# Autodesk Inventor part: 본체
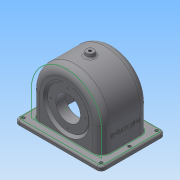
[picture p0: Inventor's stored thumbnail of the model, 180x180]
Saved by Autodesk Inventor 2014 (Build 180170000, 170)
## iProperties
Created: 2015-09
Part Number: 본체
Material: Generic
Document SubType Name: Modeling
Designer: sda1
Density: 1 g/cm^3
Appearance: Default
Author: sda1
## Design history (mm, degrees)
sketch "스케치7"
  geometry: L1 (0, 0)-(0, -40); L2 (-57, -40)-(57, -40); L3 (-57, -40)-(-57, 0); L4 (57, -40)-(57, 0); C1 r 51 at (0, 0); A1 r 57 centre (0, 0) between (-57, 0) and (57, 0)
  constraints: 8 end point, 2 centre point, 2 perpendicular, 2 point on circle, 1 coincident, 1 midpoint, 1 parallel, 1 vertical
  dimensions: "d18" = 40 distance of L1.end L1.start; "d19" = 114 distance of L2.start L2.end; "d20" = 102 diameter of C1; "d21" = 6 radial gap between concentric circles of C1 A1
extrude "돌출3" new body sketch "스케치7" distance "d22" = 77; taper "d23" = 0 deg
feature "쉘1" dims "d24" = 5
sketch "스케치11"
  geometry: L1 (0, 0)-(114, 0) reference; L2 (0, 0)-(0, -77) reference; L3 (114, -77)-(0, -77) reference; L4 (114, 0)-(114, -77) reference; L5 (5, -5)-(109, -5); L6 (109, -5)-(109, -72); L7 (109, -72)-(5, -72); L8 (5, -72)-(5, -5); L9 (-13, 13.5)-(127, 13.5); L10 (127, 13.5)-(127, -90.5); L11 (127, -90.5)-(-13, -90.5); L12 (-13, -90.5)-(-13, 13.5); L13 (57, 13.5)-(57, -90.5); L14 (57, 0)-(57, -77); 1 further point
  constraints: 20 end point, 5 midpoint, 4 parallel, 2 horizontal, 2 perpendicular
  dimensions: "d30" = 140 distance of L10.end L11.end; "d31" = 104 distance of L9.end L10.end
extrude "돌출5" join sketch "스케치11" distance "d32" = 7; taper "d33" = 0 deg
extrude "돌출6" cut sketch "스케치11" distance "d34" = 7; taper "d35" = 0 deg
node "작업 평면1"
node "작업 평면2"
sketch "스케치13"
  geometry: L1 (0, 0)-(0, -77); C1 r 6 at (0, -38.5)
  constraints: 2 end point, 1 centre point, 1 midpoint, 1 vertical
  dimensions: "d39" = 77 distance of L1.start L1.end; "d40" = 12 diameter of C1
extrude "돌출7" join sketch "스케치13" stored distance "d41" = 7; taper "d42" = 10 deg
sketch "스케치14"
  geometry: L1 (-57, -40)-(57, -40) reference; L2 (57, -40)-(57, 0) reference; L3 (-57, 0)-(-57, -40) reference; A1 r 57 centre (0, 0) between (57, 0) and (-57, 0) reference
sketch "스케치15"
  geometry: L1 (0, 0)-(0, -19); L2 (0, -19)-(28, -19); L3 (0, 0)-(43.943, 0); L4 (28, -19)-(43.943, 0)
  constraints: 8 end point, 1 parallel, 1 perpendicular, 1 vertical
  dimensions: "d43" = 19 distance of L1.start L1.end; "d44" = 50 deg angle of L2 L4; "d45" = 56 diameter of L2.end L1
revolve "회전1" sketch "스케치15" stored, may be unused: angle "d46" = 90 deg
sketch "스케치16"
  geometry: L1 (39.747, -5)-(28, -19) reference; L2 (0, 0)-(0, -3); L3 (0, -3)-(33, -3); L4 (37.416, 0)-(33, -5.263); L5 (0, 0)-(37.416, 0); L6 (33, -3)-(33, -5.263)
  constraints: 10 end point, 2 parallel, 2 perpendicular, 1 vertical
  dimensions: "d54" = 3 distance of L2.start L2.end; "d55" = 33 distance of L2.end L3.end; "d56" = 5 distance between parallel lines of L4 L1
revolve "회전2" sketch "스케치16" stored, may be unused: angle "d57" = 90 deg
sketch "스케치17"
  geometry: C1 r 31 at (0, 0); A1 r 57 centre (0, 0) between (57, 0) and (-57, 0) reference
  constraints: 1 centre point, 1 coincident
  dimensions: "d58" = 62 diameter of C1
extrude "돌출8" join sketch "스케치17" distance "d59" = 10; taper "d60" = 0 deg
sketch "스케치19"
  geometry: C1 r 20 at (0, 0); 1 further point
  constraints: 1 centre point, 1 coincident
  dimensions: "d62" = 40 diameter of C1
extrude "돌출9" cut sketch "스케치19" stored distance "d63" = 10; taper "d64" = 0 deg
sketch "스케치20"
  geometry: C1 r 6 at (0, 0) reference; 1 further point
hole "구멍1" sketch "스케치20" at (0, 0) diameter "d65" = 4.459; stored, may be unused: countersink angle "d69" = 90 deg, drill point angle "d71" = 118 deg; dims "d66" = 6, "d67" = 4, "d68" = 2, "d70" = 8
sketch "스케치21" dims "d73" = 56
  geometry: L1 (0, 0)-(0, 28); L2 (0, 37.416)-(0, 43.475); 1 further point
  constraints: 4 end point, 2 vertical, 2 vertical alignment, 1 coincident, 3 other
hole "구멍2" sketch "스케치21" at (0, 28) diameter "d74" = 2.459; stored, may be unused: countersink angle "d78" = 90 deg, drill point angle "d80" = 118 deg; dims "d75" = 7, "d76" = 4, "d77" = 2, "d79" = 9
fillet "모깎기1" dims "d84" = 0.5
sketch "스케치22" dims "d86" = 48
  geometry: L1 (0, 0)-(0, 24); C1 r 31 at (0, 0) reference
  constraints: 2 end point, 1 coincident, 1 vertical, 1 vertical alignment, 2 other
hole "구멍3" sketch "스케치22" at (0, 24) diameter "d87" = 2.459; stored, may be unused: countersink angle "d91" = 90 deg, drill point angle "d93" = 118 deg; dims "d88" = 6, "d89" = 4, "d90" = 2, "d92" = 8
fillet "모깎기2" dims "d97" = 14
fillet "모깎기3" dims "d98" = 3
fillet "모깎기4" dims "d99" = 7
fillet "모깎기5" dims "d100" = 3
fillet "모깎기6" dims "d101" = 1
fillet "모깎기7" dims "d102" = 9
sketch "스케치23"
  geometry: L1 (-20.5, -43)-(69.5, -43) reference; L2 (-20.5, -47)-(-20.5, -43) reference; L3 (69.5, -47)-(-20.5, -47) reference; L4 (69.5, -43)-(69.5, -47) reference; L5 (24.5, -47)-(24.5, -17); 2 further points
  constraints: 2 end point, 1 coincident, 1 midpoint, 1 parallel, 1 other
  dimensions: "d103" = 30 distance of L5.start L5.end
feature "엠보싱1" sketch "스케치23" dims "d104" = 0.5, "d105" = 0
sketch "스케치24"
  geometry: L1 (124, 83.5)-(124, -6.5) reference; L2 (-6, 87.5)-(120, 87.5) reference; L3 (-10, -6.5)-(-10, 83.5) reference; L4 (120, -10.5)-(-6, -10.5) reference; L5 (115, 14)-(115, 63) reference; L6 (14, -1)-(100, -1) reference; L7 (-1, 63)-(-1, 14) reference; L8 (100, 78)-(14, 78) reference; A1 r 4 centre (120, -6.5) between (120, -10.5) and (124, -6.5) reference; A2 r 4 centre (120, 83.5) between (124, 83.5) and (120, 87.5) reference; A3 r 4 centre (-6, 83.5) between (-6, 87.5) and (-10, 83.5) reference; A4 r 4 centre (-6, -6.5) between (-10, -6.5) and (-6, -10.5) reference; A5 r 15 centre (100, 63) between (115, 63) and (100, 78) reference; A6 r 15 centre (100, 14) between (100, -1) and (115, 14) reference; A7 r 15 centre (14, 14) between (-1, 14) and (14, -1) reference; A8 r 15 centre (14, 63) between (14, 78) and (-1, 63) reference; 1 further point
fillet "모깎기8" dims "d106" = 3
sketch "스케치25"
  geometry: L1 (100, 78)-(14, 78) reference; L2 (-6, 83.5)-(-6, 39.5); A1 r 4 centre (-6, 83.5) between (-6, 87.5) and (-10, 83.5) reference; A2 r 4 centre (-6, -6.5) between (-10, -6.5) and (-6, -10.5) reference; 1 further point
  constraints: 2 end point, 1 perpendicular
  dimensions: "d108" = 44 distance of L2.start L2.end
hole "구멍4" sketch "스케치25" at (-6, 39.5), (-6, 83.5), (-6, -6.5) diameter "d109" = 5; stored, may be unused: countersink angle "d113" = 90 deg, drill point angle "d115" = 118 deg; dims "d110" = 5, "d111" = 4, "d112" = 2, "d114" = 8
node "작업 평면3"
node "솔리드2"
pattern_circular "원형 패턴1" dims angle "d82" = 360 deg
pattern_circular "원형 패턴2" dims angle "d95" = 360 deg
mirror "대칭1"
node "투영된 루프1"
other parameters: "d38" = 6
